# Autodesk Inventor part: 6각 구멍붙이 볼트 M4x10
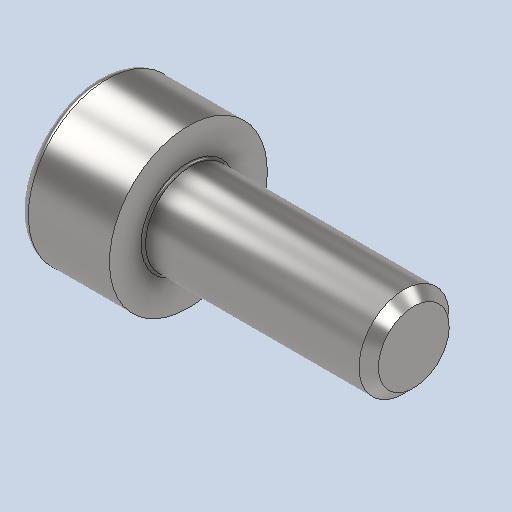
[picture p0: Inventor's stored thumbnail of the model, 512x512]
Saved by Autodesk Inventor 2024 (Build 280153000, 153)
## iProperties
Created: 2025-11
Part Number: 6각 구멍붙이 볼트 M4x10
Material: 강철, 연강
Description: 6각머리 태핑 나사
Document SubType Name: Modeling
Designer: Edu07
Density: 7.85 g/cm^3
Appearance: 기본값
Author: jhkim
Sending System: Autodesk Inventor 2026
Preprocessor: ST-DEVELOPER v20.1
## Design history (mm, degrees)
node "6각 구멍붙이 볼트 M4x101"
node "솔리드1"
body "Solid1"
